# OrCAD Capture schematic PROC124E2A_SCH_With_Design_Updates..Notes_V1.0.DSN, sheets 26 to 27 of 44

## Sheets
26 25. TEST AUTOMATION: size C; title: TEST AUTOMATION
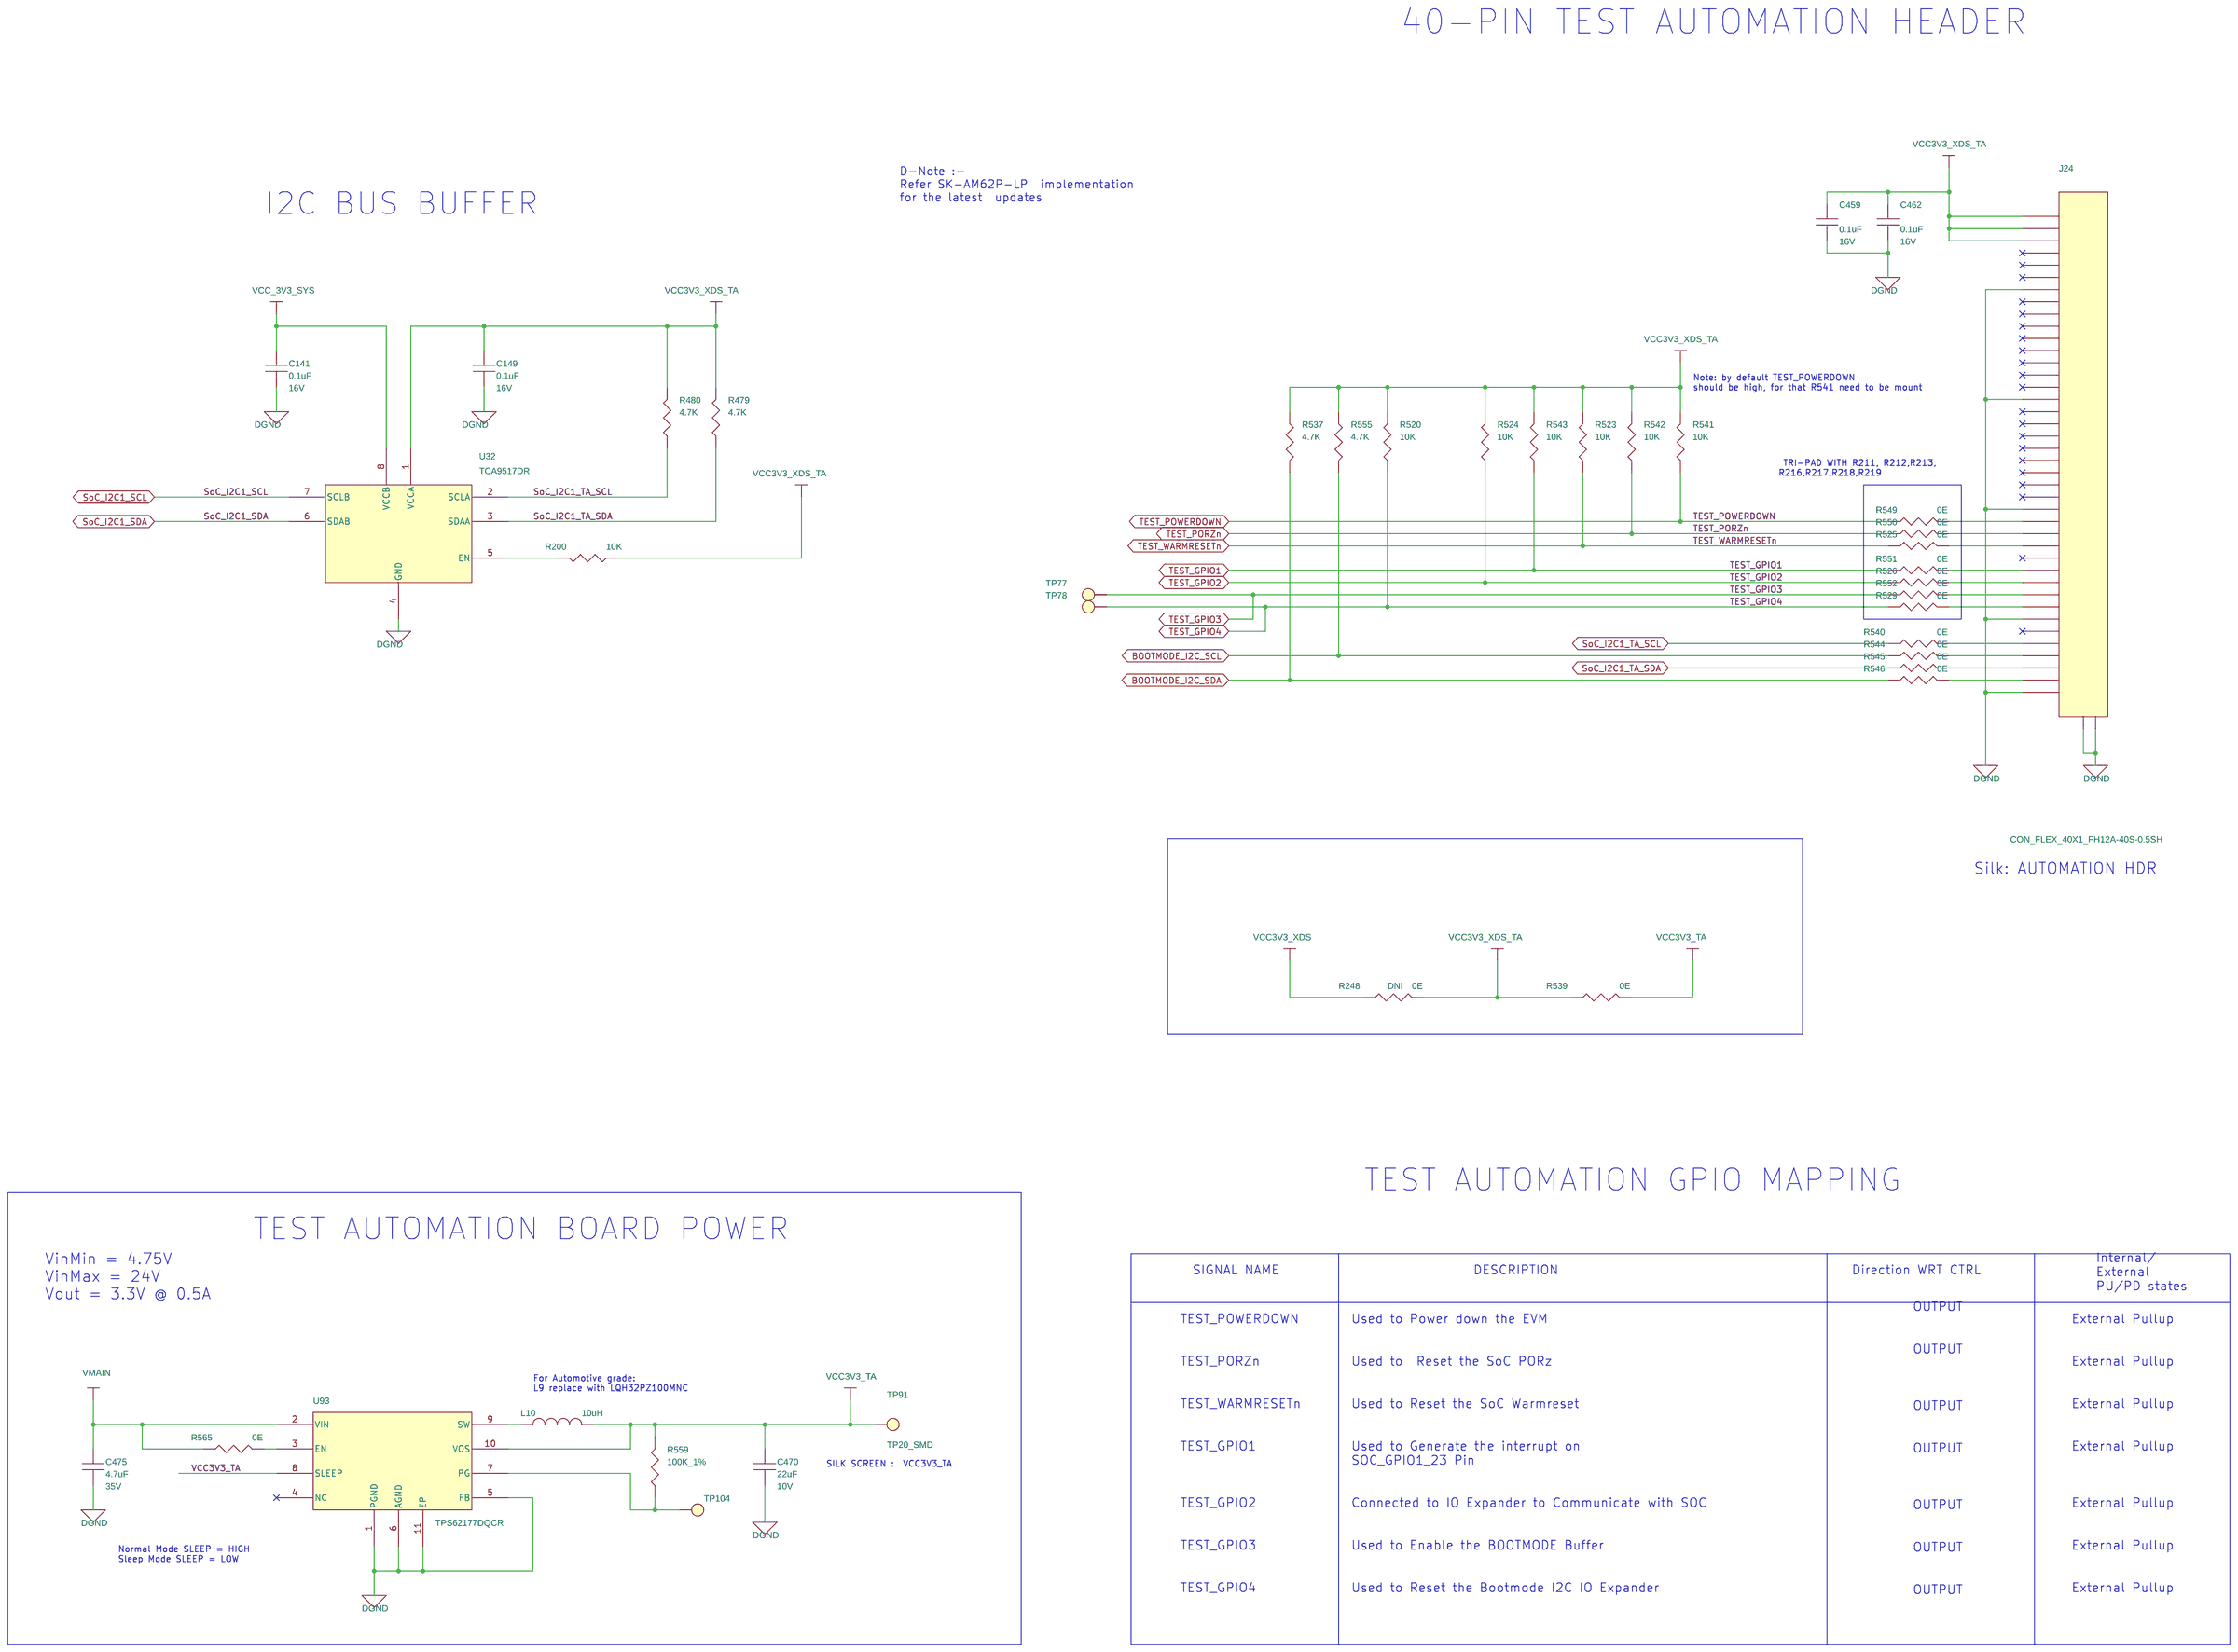
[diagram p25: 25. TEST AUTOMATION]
27 26. BOOT MODE BUFFER & SWITCHES: size C; title: BOOT MODE BUFFER & SWITCHES
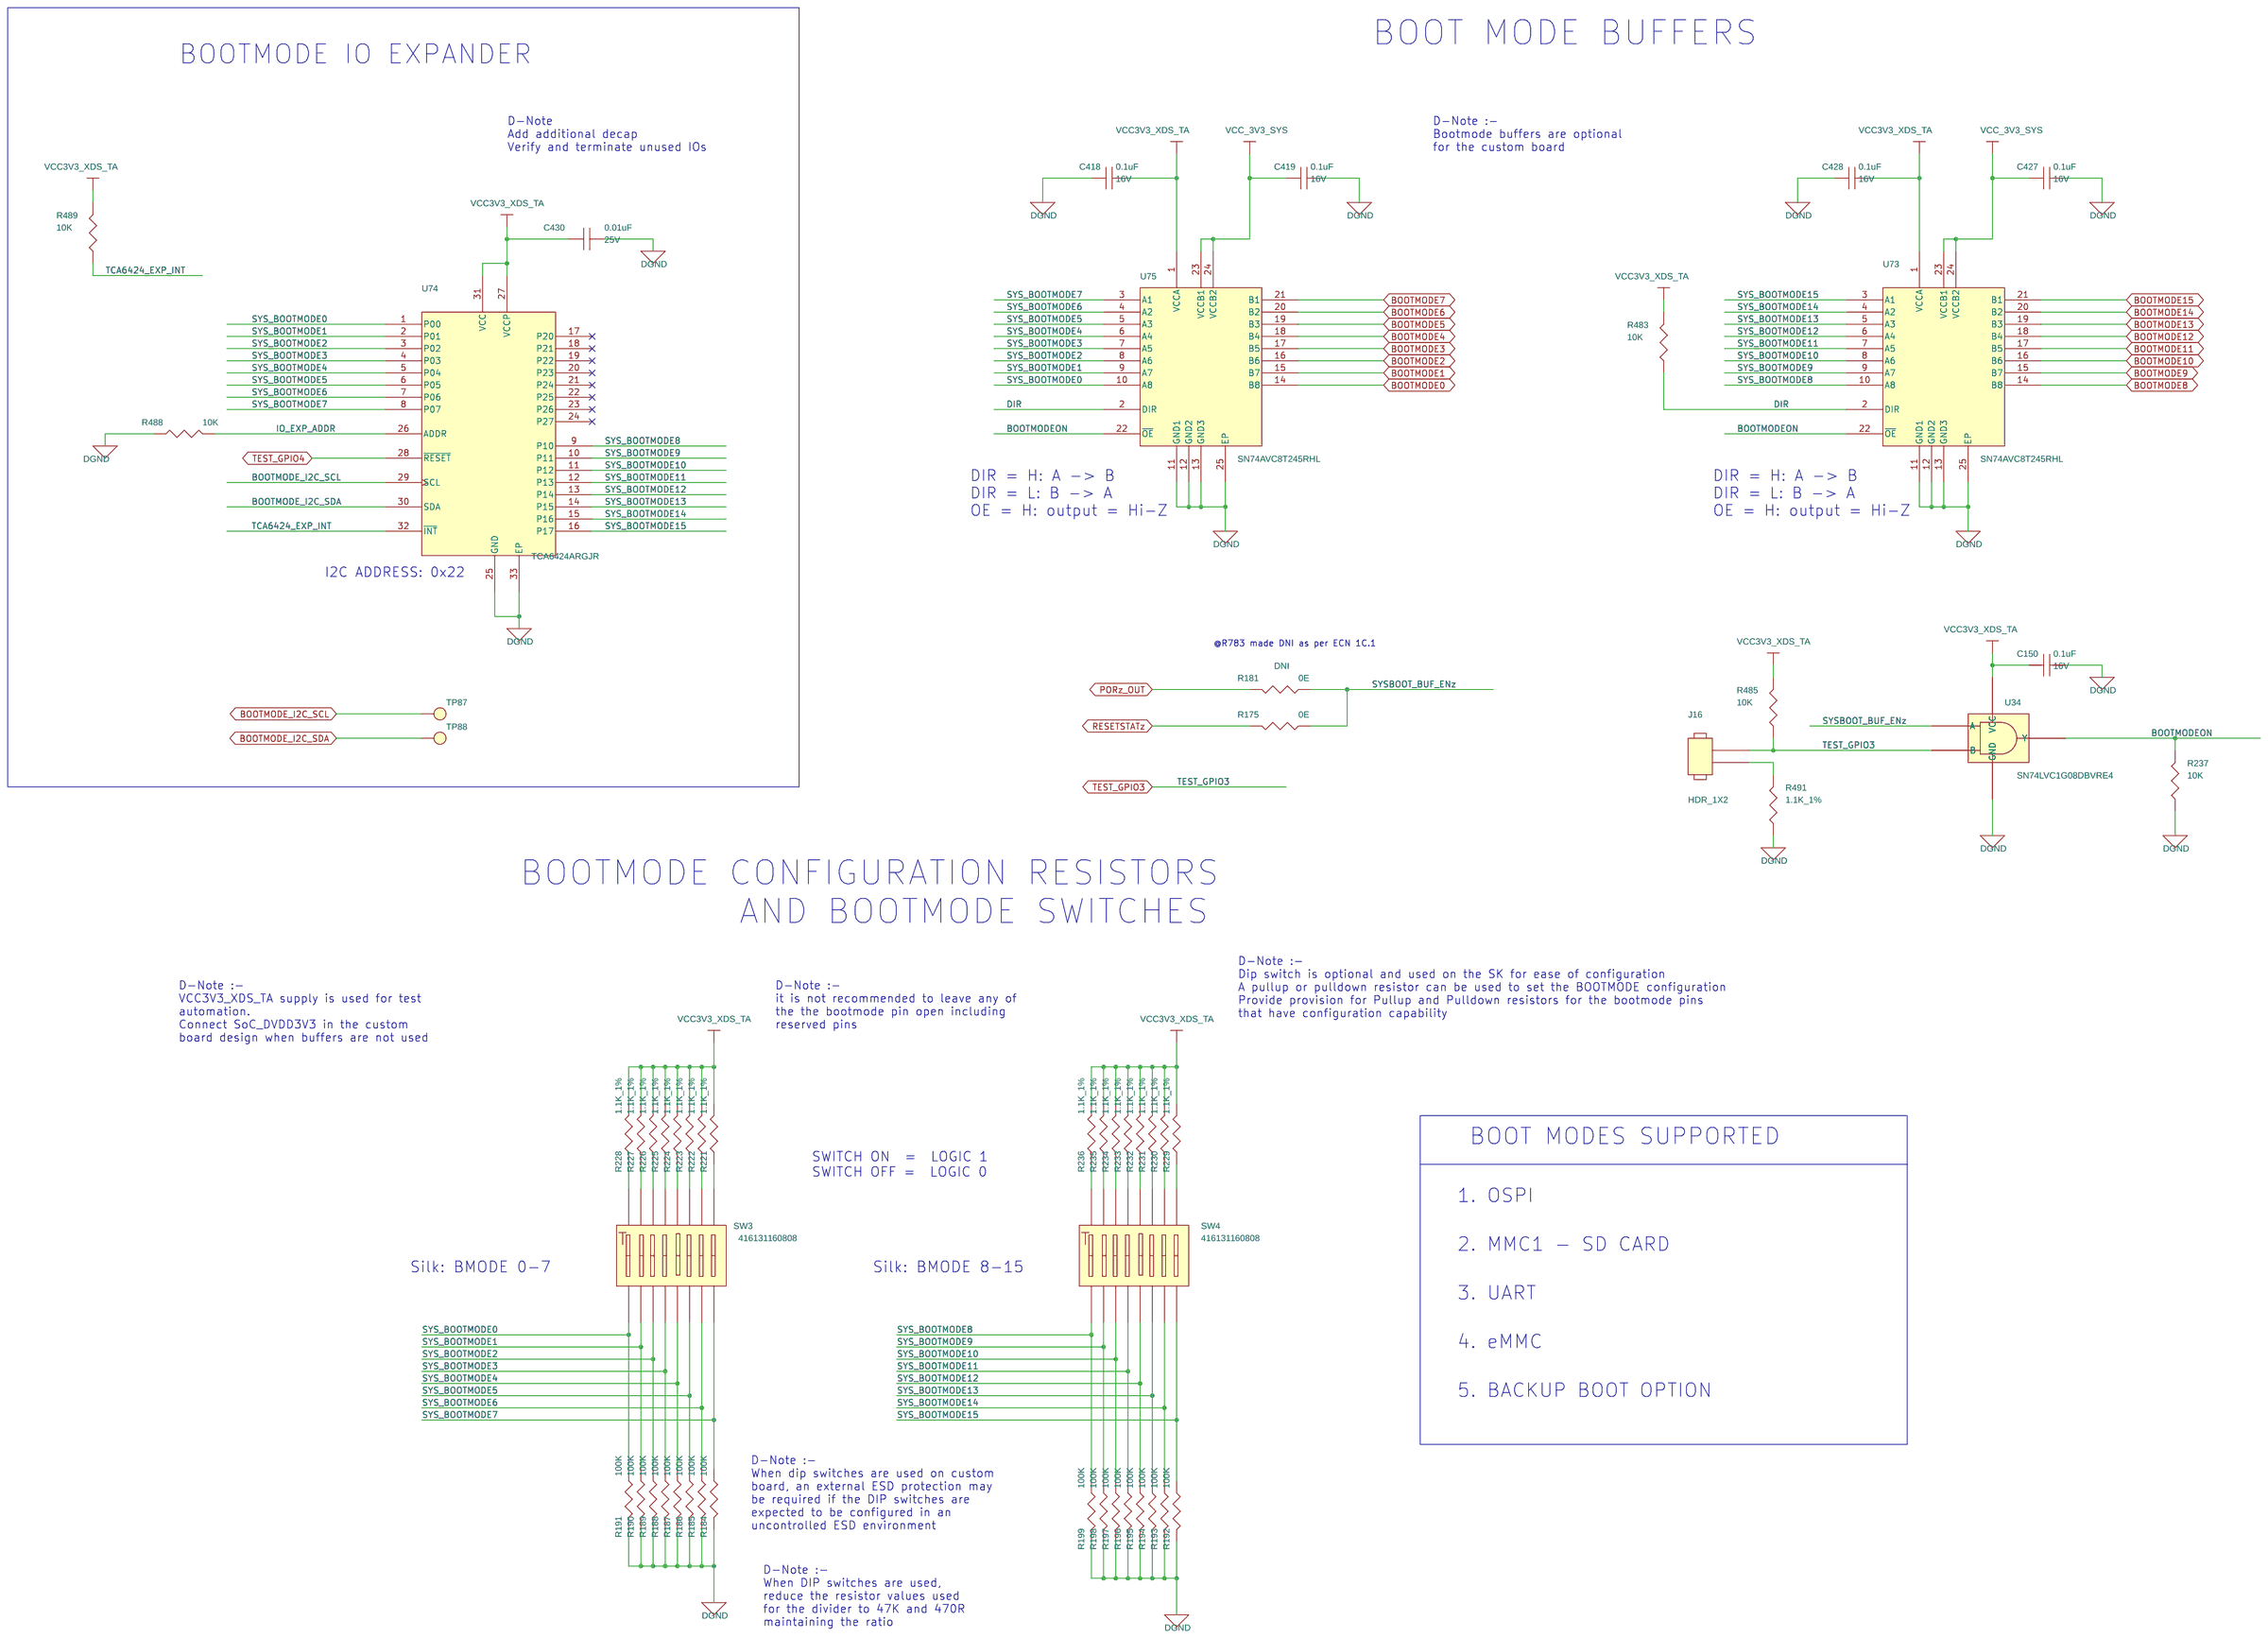
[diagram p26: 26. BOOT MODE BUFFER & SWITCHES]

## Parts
sheet 25. TEST AUTOMATION
C141  0.1uF  [CAP0201_0-5]
C149  0.1uF  [CAP0201_0-5]
C459  0.1uF  [CAP0201_0-5]
C462  0.1uF  [CAP0201_0-5]
C470  22uF  [CAP0603_1]
C475  4.7uF  [CAP0603_1]
J24  CON_FLEX_40X1_FH12A-40S-0.5SH  [CON_FLEX40X1_FH12A_S_R_S]
L10  10uH  [IND_1277AS-H_130X110_SMD_1-2]
R200  10K  [RES0201_0-5]
R248  0E  [RES0805_0-75]
R479  4.7K  [RES0201_0-5]
R480  4.7K  [RES0201_0-5]
R520  10K  [RES0201_0-5]
R523  10K  [RES0201_0-5]
R524  10K  [RES0201_0-5]
R525  0E  [RES0201_0-5]
R526  0E  [RES0201_0-5]
R529  0E  [RES0201_0-5]
R537  4.7K  [RES0201_0-5]
R539  0E  [RES0805_0-75]
R540  0E  [RES0201_0-5]
R541  10K  [RES0201_0-5]
R542  10K  [RES0201_0-5]
R543  10K  [RES0201_0-5]
R544  0E  [RES0201_0-5]
R545  0E  [RES0201_0-5]
R546  0E  [RES0201_0-5]
R549  0E  [RES0201_0-5]
R550  0E  [RES0201_0-5]
R551  0E  [RES0201_0-5]
R552  0E  [RES0201_0-5]
R555  4.7K  [RES0201_0-5]
R559  100K_1%  [RES0402_0-5]
R565  0E  [RES0402_0-5]
TP77  TP20_SMD  [TP20_SMD]
TP78  TP20_SMD  [TP20_SMD]
TP91  TP20_SMD  [TP20_SMD]
TP104  TP20_SMD  [TP20_SMD]
U32  TCA9517DR  [SOIC8_1-8]
U93  TPS62177DQCR  [WSON10_19-68_80X120_0-8]
sheet 26. BOOT MODE BUFFER & SWITCHES
C150  0.1uF  [CAP0201_0-5]
C418  0.1uF  [CAP0201_0-5]
C419  0.1uF  [CAP0201_0-5]
C427  0.1uF  [CAP0201_0-5]
C428  0.1uF  [CAP0201_0-5]
C430  0.01uF  [CAP0201_0-5]
J16  HDR_1X2  [HDR_1X2_90120-0122_S_T_5-6]
R175  0E  [RES0201_0-5]
R181  0E  [RES0201_0-5]
R184  100K  [RES0201_0-5]
R185  100K  [RES0201_0-5]
R186  100K  [RES0201_0-5]
R187  100K  [RES0201_0-5]
R188  100K  [RES0201_0-5]
R189  100K  [RES0201_0-5]
R190  100K  [RES0201_0-5]
R191  100K  [RES0201_0-5]
R192  100K  [RES0201_0-5]
R193  100K  [RES0201_0-5]
R194  100K  [RES0201_0-5]
R195  100K  [RES0201_0-5]
R196  100K  [RES0201_0-5]
R197  100K  [RES0201_0-5]
R198  100K  [RES0201_0-5]
R199  100K  [RES0201_0-5]
R221  1.1K_1%  [RES0201_0-5]
R222  1.1K_1%  [RES0201_0-5]
R223  1.1K_1%  [RES0201_0-5]
R224  1.1K_1%  [RES0201_0-5]
R225  1.1K_1%  [RES0201_0-5]
R226  1.1K_1%  [RES0201_0-5]
R227  1.1K_1%  [RES0201_0-5]
R228  1.1K_1%  [RES0201_0-5]
R229  1.1K_1%  [RES0201_0-5]
R230  1.1K_1%  [RES0201_0-5]
R231  1.1K_1%  [RES0201_0-5]
R232  1.1K_1%  [RES0201_0-5]
R233  1.1K_1%  [RES0201_0-5]
R234  1.1K_1%  [RES0201_0-5]
R235  1.1K_1%  [RES0201_0-5]
R236  1.1K_1%  [RES0201_0-5]
R237  10K  [RES0201_0-5]
R483  10K  [RES0201_0-5]
R485  10K  [RES0201_0-5]
R488  10K  [RES0201_0-5]
R489  10K  [RES0201_0-5]
R491  1.1K_1%  [RES0201_0-5]
SW3  416131160808  [SW16_416131160808_460X230_SMD_2-7]
SW4  416131160808  [SW16_416131160808_460X230_SMD_2-7]
TP87  TP20_SMD  [TP20_SMD]
TP88  TP20_SMD  [TP20_SMD]
U34  SN74LVC1G08DBVRE4  [SOT23-5]
U73  SN74AVC8T245RHL  [QFN24_19-68_220X140_1]
U74  TCA6424ARGJR  [QFN32_19-68_200X200]
U75  SN74AVC8T245RHL  [QFN24_19-68_220X140_1]

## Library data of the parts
C141 C149 C150 C418 C419 C427 C428 C459 C462 = CAP: CAP CERAMIC 0.1uF 16V 10% X5R 0201; Alt_Mfr_name: YAGEO AMERICA; Alt_Mfr_part_number: CC0402KRX5R8BB104; Chkd/date: MANIRAJA/230118; Crtd /date: MANIRAJA/230118; Custom_Duty: 15%; Customs_HS_Code: 85322990; Distributor_name: DIGIKEY; Distributor_part_number: 490-14305-1-ND; Footprint Path: Y:\MIS_DATABASE\Library\ALTIUM_TOOL\PCB_FOOTPRINTS\Altium_Footprint_Lib.PcbLib; Height: 0.33MM; Library Path: Y:\MIS_DATABASE\Library\ALTIUM_TOOL\SCHEMATICS_PARTS\MS_DISCRETE_Library.schlib; Mfr_name: MURATA; Mfr_part_number: GRM033R61C104KE14D; Mistral Part No: 120009030072-R; Package: 0201; Part_type: CAPACITORS\CERAMIC; Project: TI_MAXIE_CPB; RoHS: RoHS; Temperature: -55°C+85°C; Tolerance: 10%; Voltage: 16V; Wattage: NA; Weight: 0.33mg; Datasheet: Y:\MIS_DATABASE\DATASHEETS\CAPACITORS\GRM033R61C104KE14.PDF
C470 = CAP: CAP CERAMIC 22uF 10V 20% X5R 0603; Chkd/date: MANIRAJA/230118; Crtd /date: MANIRAJA/230118; Custom_Duty: 15%; Customs_HS_Code: 85322990; Distributor_name: DIGIKEY; Distributor_part_number: 490-10476-1-ND; Footprint Path: Y:\MIS_DATABASE\Library\ALTIUM_TOOL\PCB_FOOTPRINTS\Altium_Footprint_Lib.PcbLib; Height: 1.00MM; Library Path: Y:\MIS_DATABASE\Library\ALTIUM_TOOL\SCHEMATICS_PARTS\MS_DISCRETE_Library.schlib; Mfr_name: MURATA; Mfr_part_number: GRM188R61A226ME15D; Mistral Part No: 120014100009-R; Package: 0603; Part_type: CAPACITORS\CERAMIC; Project: TI_MAXIE_CPB; RoHS: RoHS; Temperature: -55°C+85°C; Tolerance: 20%; Voltage: 10V; Wattage: NA; Weight: 6.3mg; Datasheet: Y:\MIS_DATABASE\DATASHEETS\CAPACITORS\GRM188R61A226ME15.PDF
C475 = CAP: CAP CERAMIC 4.7uF 35V 20% X5R 0603; Chkd/date: MANIRAJA/120520; Crtd /date: ALVY/120520; Custom_Duty: 15%; Customs_HS_Code: 85322990; Distributor_name: DIGIKEY; Distributor_part_number: 490-11995-1-ND; Footprint Path: Y:\MIS_DATABASE\Library\ALTIUM_TOOL\PCB_FOOTPRINTS\Altium_Footprint_Lib.PcbLib; Height: 1.00MM; Library Path: Y:\MIS_DATABASE\Library\ALTIUM_TOOL\SCHEMATICS_PARTS\MS_DISCRETE_Library.schlib; Mfr_name: MURATA; Mfr_part_number: GRM188R6YA475ME15D; Mistral Part No: 120020050017-R; Package: 0603; Part_type: CAPACITORS\CERAMIC; Project: SD865_NANOSOM; RoHS: RoHS; Temperature: -55°C+85°C; Tolerance: 20%; Voltage: 35V; Wattage: NA; Weight: 6.3mg; Datasheet: Y:\MIS_DATABASE\DATASHEETS\CAPACITORS\GRM188R6YA475ME15.PDF
J24 = CON_FLEX_40X1_FH12A-40S-0.5SH: CON FPC 40X1 0.50MM PITCH RT TOP SMD; Chkd/date: SHREESHAIL/201106; Crtd /date: MAZHAR/171106; Custom_Duty: 24%; Customs_HS_Code: 85369090; Distributor_name: DIGIKEY; Distributor_part_number: HFK40CT-ND; Height: 2.00MM; Mfr_name: HIROSE ELECTRIC EUROPE; Mfr_part_number: FH12A-40S-0.5SH(55); Mistral Part No: 150009030176-R; Package: SMD; Part_type: CONNECTOR\FPC; Project: PMP LCD BOARD; Datasheet: Y:\MIS_DATABASE\DATASHEETS\CONNECTORS\FH12SERIES.PDF
L10 = INDUCTOR: IND POWER 10uH 900mA 20% SMD; Chkd/date: MANIRAJA/200921; Crtd /date: ALVY/200921; Custom_Duty: 24%; Customs_HS_Code: 85369090; Distributor_name: DIGIKEY; Distributor_part_number: 490-10589-1-ND; Footprint Path: Y:\MIS_DATABASE\Library\ALTIUM_TOOL\PCB_FOOTPRINTS\Altium_Footprint_Lib.PcbLib; Height: 1.20MM; Library Path: Y:\MIS_DATABASE\Library\ALTIUM_TOOL\SCHEMATICS_PARTS\MS_DISCRETE_Library.schlib; Mfr_name: MURATA; Mfr_part_number: 1277AS-H-100M=P2; Mistral Part No: 130021090022-R; Package: SMD; Project: TI_AM62x SKEVM_BRD; RoHS: RoHS; Temperature: -40°C+85°C; Tolerance: 20%; Voltage: NA; Wattage: NA; Weight: NA; Datasheet: Y:\MIS_DATABASE\DATASHEETS\DISCRETES\INDUCTORS\MURATA-1277AS-H.PDF
R200 R237 R483 R485 R488 R489 R520 R523 R524 R541-R543 = RESISTOR: RES 10K 1/20W 5% 0201; Chkd/date: MANIRAJA/050517; Crtd /date: MANIRAJA/050517; Custom_Duty: 15%; Customs_HS_Code: 85332119; Distributor_name: DIGIKEY; Distributor_part_number: 311-10KNCT-ND; Footprint Path: Y:\MIS_DATABASE\Library\ALTIUM_TOOL\PCB_FOOTPRINTS\Altium_Footprint_Lib.PcbLib; Height: 0.26MM; Library Path: Y:\MIS_DATABASE\Library\ALTIUM_TOOL\SCHEMATICS_PARTS\MS_DISCRETE_Library.schlib; Mfr_name: YAGEO AMERICA; Mfr_part_number: RC0201JR-0710KL; Mistral Part No: 110010070051-R; Package: 0201; Part_type: RESISTORS\FIXED; Project: GOLDEN-I LITE; RoHS: RoHS; Temperature: -55°C+125°C; Tolerance: 5%; Voltage: NA; Wattage: 1/20W; Weight: 0.17mg; Datasheet: Y:\MIS_DATABASE\DATASHEETS\RESISTORS\RCXXXXL-SER_MAR18.PDF
R248 = RESISTOR: RES 0E 1/8W 5% 0805; Assembly_Instruction: DNI; Chkd/date: VASANTHA/130416; Crtd /date: JEBRAN/020316; Custom_Duty: 15%; Customs_HS_Code: 85332119; Distributor_name: DIGIKEY; Distributor_part_number: 311-0.0ARCT-ND; Footprint Path: Y:\MIS_DATABASE\Library\ALTIUM_TOOL\PCB_FOOTPRINTS\Altium_Footprint_Lib.PcbLib; Height: 0.60MM; Library Path: Y:\MIS_DATABASE\Library\ALTIUM_TOOL\SCHEMATICS_PARTS\MS_DISCRETE_Library.schlib; Mfr_name: YAGEO AMERICA; Mfr_part_number: RC0805JR-070RL; Mistral Part No: 110009030074-R; Package: 0805; Part_type: RESISTORS\FIXED; Project: ZK_BIOMETRIC; RoHS: RoHS; Temperature: -55°C+155°C; Tolerance: 5%; Voltage: NA; Wattage: 1/8W; Weight: 5.5mg; Datasheet: Y:\MIS_DATABASE\DATASHEETS\RESISTORS\RCXXXXL-SER_MAR18.PDF
R479 R480 R537 R555 = RESISTOR: RES 4.7K 1/20W 5% 0201; Chkd/date: MANIRAJA/200921; Crtd /date: ALVY/200921; Custom_Duty: 15%; Customs_HS_Code: 85332119; Distributor_name: DIGIKEY; Distributor_part_number: 311-4.7KNCT-ND; Footprint Path: Y:\MIS_DATABASE\Library\ALTIUM_TOOL\PCB_FOOTPRINTS\Altium_Footprint_Lib.PcbLib; Height: 0.26MM; Library Path: Y:\MIS_DATABASE\Library\ALTIUM_TOOL\SCHEMATICS_PARTS\MS_DISCRETE_Library.schlib; Mfr_name: YAGEO AMERICA; Mfr_part_number: RC0201JR-074K7L; Mistral Part No: 110021090007-R; Package: 0201; Part_type: RESISTORS\FIXED; Project: TI_AM62x SKEVM_BRD; RoHS: RoHS; Temperature: -55°C+125°C; Tolerance: 5%; Voltage: NA; Wattage: 1/20W; Weight: 0.17mg; Datasheet: Y:\MIS_DATABASE\DATASHEETS\RESISTORS\RCXXXXL-SER_MAR18.PDF
R175 R525 R526 R529 R540 R544-R546 R549-R552 = RESISTOR: RES 0E 1/20W 5% 0201; Chkd/date: NAVEED/301214; Crtd /date: MUDDU/120710; Custom_Duty: 15%; Customs_HS_Code: 85332119; Distributor_name: DIGIKEY; Distributor_part_number: 311-0.0NCT-ND; Footprint Path: Y:\MIS_DATABASE\Library\ALTIUM_TOOL\PCB_FOOTPRINTS\Altium_Footprint_Lib.PcbLib; Height: 0.26MM; Library Path: Y:\MIS_DATABASE\Library\ALTIUM_TOOL\SCHEMATICS_PARTS\MS_DISCRETE_Library.schlib; Mfr_name: YAGEO AMERICA; Mfr_part_number: RC0201JR-070RL; Mistral Part No: 110010070067-R; Package: 0201; Part_type: RESISTORS\FIXED; Project: PB_BUGBASE; RoHS: RoHS; Temperature: -55°C+125°C; Tolerance: 5%; Voltage: NA; Wattage: 1/20W; Weight: 0.17mg; Datasheet: Y:\MIS_DATABASE\DATASHEETS\RESISTORS\RCXXXXL-SER_MAR18.PDF
R539 = RESISTOR: RES 0E 1/8W 5% 0805; Chkd/date: VASANTHA/130416; Crtd /date: JEBRAN/020316; Custom_Duty: 15%; Customs_HS_Code: 85332119; Distributor_name: DIGIKEY; Distributor_part_number: 311-0.0ARCT-ND; Footprint Path: Y:\MIS_DATABASE\Library\ALTIUM_TOOL\PCB_FOOTPRINTS\Altium_Footprint_Lib.PcbLib; Height: 0.60MM; Library Path: Y:\MIS_DATABASE\Library\ALTIUM_TOOL\SCHEMATICS_PARTS\MS_DISCRETE_Library.schlib; Mfr_name: YAGEO AMERICA; Mfr_part_number: RC0805JR-070RL; Mistral Part No: 110009030074-R; Package: 0805; Part_type: RESISTORS\FIXED; Project: ZK_BIOMETRIC; RoHS: RoHS; Temperature: -55°C+155°C; Tolerance: 5%; Voltage: NA; Wattage: 1/8W; Weight: 5.5mg; Datasheet: Y:\MIS_DATABASE\DATASHEETS\RESISTORS\RCXXXXL-SER_MAR18.PDF
R559 = RESISTOR: RES 100K 1/10W 1% 0402; Chkd/date: VASANTHA/201216; Crtd /date: MAZHAR/130306; Custom_Duty: 15%; Customs_HS_Code: 85332119; Distributor_name: DIGIKEY; Distributor_part_number: P100KLCT-ND; Footprint Path: Y:\MIS_DATABASE\Library\ALTIUM_TOOL\PCB_FOOTPRINTS\Altium_Footprint_Lib.PcbLib; Height: 0.40MM; Library Path: Y:\MIS_DATABASE\Library\ALTIUM_TOOL\SCHEMATICS_PARTS\MS_DISCRETE_Library.schlib; Mfr_name: PANASONIC-ECG; Mfr_part_number: ERJ-2RKF1003X; Mistral Part No: 110009030187-R; Package: 0402; Part_type: RESISTORS\FIXED; Project: J32; RoHS: RoHS; Temperature: -55°C+155°C; Tolerance: 1%; Voltage: NA; Wattage: 1/10W; Weight: 0.8mg; Datasheet: Y:\MIS_DATABASE\DATASHEETS\RESISTORS\PAN-ERJSER_NOV17.PDF
R565 = RESISTOR: RES 0E 1/16W JUMPER 0402; Chkd/date: VASANTHA/201216; Crtd /date: MUDDU/190810; Custom_Duty: 15%; Customs_HS_Code: 85332119; Distributor_name: DIGIKEY; Distributor_part_number: 541-0.0JCT-ND; Footprint Path: Y:\MIS_DATABASE\Library\ALTIUM_TOOL\PCB_FOOTPRINTS\Altium_Footprint_Lib.PcbLib; Height: 0.40MM; Library Path: Y:\MIS_DATABASE\Library\ALTIUM_TOOL\SCHEMATICS_PARTS\MS_DISCRETE_Library.schlib; Mfr_name: VISHAY; Mfr_part_number: CRCW04020000Z0ED; Mistral Part No: 110010080019-R; Package: 0402; Part_type: RESISTORS\FIXED; Project: PB_BUGBASE; RoHS: RoHS; Temperature: -55°C+155°C; Tolerance: NA; Voltage: NA; Wattage: 1/16W; Weight: 0.65mg; Datasheet: Y:\MIS_DATABASE\DATASHEETS\RESISTORS\CRCW0603.PDF
TP77 TP78 TP87 TP88 TP104 = TESTPOINT: TESTPOINT CIR 20 SMD; Chkd/date: SHREESHAIL/171006; Crtd /date: MAZHAR/171006; Custom_Duty: NA; Customs_HS_Code: NA; Distributor_name: NA; Distributor_part_number: NA; Footprint Path: Y:\MIS_DATABASE\Library\ALTIUM_TOOL\PCB_FOOTPRINTS\Altium_Footprint_Lib.PcbLib; Height: NA; Library Path: Y:\MIS_DATABASE\Library\ALTIUM_TOOL\SCHEMATICS_PARTS\MS_DISCRETE_Library.schlib; MECHANICAL 3D STEP FILE: NA; Mfr_name: LOCAL; Mistral Part No: NA; Package: SMD; Project: BT MODULE_CSRBC04; RoHS: NA; Temperature: NA; Tolerance: NA; Voltage: NA; Wattage: NA; Weight: NA; Datasheet: NA
TP91 = TESTPOINT: TESTPOINT CIR 20 SMD; Chkd/date: SHREESHAIL/171006; Crtd /date: MAZHAR/171006; Custom_Duty: NA; Customs_HS_Code: NA; Distributor_name: NA; Distributor_part_number: NA; Footprint Path: Y:\MIS_DATABASE\Library\ALTIUM_TOOL\PCB_FOOTPRINTS\Altium_Footprint_Lib.PcbLib; Height: NA; Library Path: Y:\MIS_DATABASE\Library\ALTIUM_TOOL\SCHEMATICS_PARTS\MS_DISCRETE_Library.schlib; MECHANICAL 3D STEP FILE: NA; Manufacturer: LOCAL; Mfr_name: LOCAL; Mistral Part No: NA; Package: SMD; Project: BT MODULE_CSRBC04; RoHS: NA; Temperature: NA; Tolerance: NA; Voltage: NA; Wattage: NA; Weight: NA; Datasheet: NA
U32 = TCA9517DGKR_VSSOP8: IC 2-CHANNEL BI-DIR LEVEL-SHIFTING I2C BUS REPEATER SOIC8; Chkd/date: MANIRAJA/171121; Crtd /date: ALVY/161121; Custom_Duty: 15%; Customs_HS_Code: 85423100; Distributor_name: DIGIKEY; Distributor_part_number: 296-39221-1-ND; Footprint Path: Y:\MIS_DATABASE\Library\ALTIUM_TOOL\PCB_FOOTPRINTS\Altium_Footprint_Lib.PcbLib; Height: 1.75MM; Library Path: Y:\MIS_DATABASE\Library\ALTIUM_TOOL\SCHEMATICS_PARTS\MS_MISCINTERFACE_Library.schlib; Mfr_name: TEXAS INSTRUMENTS; Mistral Part No: 141021110017-R; Package: SOIC8; Part_type: ICS\INTERFACE\LEVEL TRANSLATOR; Project: EXCITER MULTI-CH RX UNIT; RoHS: RoHS; Temperature: -40°C+85°C; Tolerance: NA; Voltage: NA; Wattage: NA; Weight: 540mg; Datasheet: Y:\MIS_DATABASE\DATASHEETS\ICS\INTERFACE\TCA9517.PDF
U93 = TPS62177_WSON10: IC 3.3V 0.5A STEP DOWN CONVERTER WITH SLEEP MODE WSON10; Chkd/date: MANIRAJA/170719; Crtd /date: MANIRAJA/170719; Custom_Duty: 15%; Customs_HS_Code: 85423100; Distributor_name: DIGIKEY; Distributor_part_number: 296-41856-1-ND; Footprint Path: Y:\MIS_DATABASE\Library\ALTIUM_TOOL\PCB_FOOTPRINTS\Altium_Footprint_Lib.PcbLib; Height: 0.80MM; Library Path: Y:\MIS_DATABASE\Library\ALTIUM_TOOL\SCHEMATICS_PARTS\MS_MISCPOWER_Library.schlib; Mfr_name: TEXAS INSTRUMENTS; Mistral Part No: 142019070007-R; Package: WSON10; Part_type: ICS\POWER\DC-DC CONVERTER; Project: TI_MAXIE_CPB; RoHS: RoHS; Temperature: -40°C+85°C; Tolerance: NA; Voltage: NA; Wattage: NA; Weight: 15mg; Datasheet: Y:\MIS_DATABASE\DATASHEETS\ICS\POWER\TPS62177.PDF
C430 = CAP: CAP CERAMIC 0.01uF 25V 10% X5R 0201; Chkd/date: MANIRAJA/230118; Crtd /date: MANIRAJA/230118; Custom_Duty: 15%; Customs_HS_Code: 85322990; Distributor_name: DIGIKEY; Distributor_part_number: GRM033R61E103KA12J-ND; Footprint Path: Y:\MIS_DATABASE\Library\ALTIUM_TOOL\PCB_FOOTPRINTS\Altium_Footprint_Lib.PcbLib; Height: 0.33MM; Library Path: Y:\MIS_DATABASE\Library\ALTIUM_TOOL\SCHEMATICS_PARTS\MS_DISCRETE_Library.schlib; Mfr_name: MURATA; Mfr_part_number: GRM033R61E103KA12J; Mistral Part No: 120018010007-R; Package: 0201; Part_type: CAPACITORS\CERAMIC; Project: TI_MAXIE_CPB; RoHS: RoHS; Temperature: -55°C+85°C; Tolerance: 10%; Voltage: 25V; Wattage: NA; Weight: 0.33mg; Datasheet: Y:\MIS_DATABASE\DATASHEETS\CAPACITORS\GRM033R61E103KA12.PDF
J16 = HEADER_2X1: CON HDR 1X2 2.54MM PITCH ST TH; Chkd/date: NAVEED/210714; Crtd /date: USMAN/031012; Custom_Duty: 24%; Customs_HS_Code: 85369090; Distributor_name: DIGIKEY; Distributor_part_number: WM8072-ND; Footprint Path: Y:\MIS_DATABASE\Library\ALTIUM_TOOL\PCB_FOOTPRINTS\Altium_Footprint_Lib.PcbLib; Height: 5.60MM; Library Path: Y:\MIS_DATABASE\Library\ALTIUM_TOOL\SCHEMATICS_PARTS\MS_CONNECTOR_Library.schlib; Mfr_name: MOLEX; Mfr_part_number: 90120-0122; Mistral Part No: 150012100005-R; Package: THRU-HOLE; Part_type: CONNECTOR\HEADERS; Project: NPOL_FEP; RoHS: RoHS; Temperature: -55°C+125°C; Tolerance: NA; Voltage: NA; Wattage: NA; Weight: 122mg; Datasheet: Y:\MIS_DATABASE\DATASHEETS\CONNECTORS\90120-XX.PDF
R181 = RESISTOR: RES 0E 1/20W 5% 0201; Assembly_Instruction: DNI; Chkd/date: NAVEED/301214; Crtd /date: MUDDU/120710; Custom_Duty: 15%; Customs_HS_Code: 85332119; Distributor_name: DIGIKEY; Distributor_part_number: 311-0.0NCT-ND; Footprint Path: Y:\MIS_DATABASE\Library\ALTIUM_TOOL\PCB_FOOTPRINTS\Altium_Footprint_Lib.PcbLib; Height: 0.26MM; Library Path: Y:\MIS_DATABASE\Library\ALTIUM_TOOL\SCHEMATICS_PARTS\MS_DISCRETE_Library.schlib; Mfr_name: YAGEO AMERICA; Mfr_part_number: RC0201JR-070RL; Mistral Part No: 110010070067-R; Package: 0201; Part_type: RESISTORS\FIXED; Project: PB_BUGBASE; RoHS: RoHS; Temperature: -55°C+125°C; Tolerance: 5%; Voltage: NA; Wattage: 1/20W; Weight: 0.17mg; Datasheet: Y:\MIS_DATABASE\DATASHEETS\RESISTORS\RCXXXXL-SER_MAR18.PDF
R184-R199 = RESISTOR: RES 100K 1/20W 5% 0201; Chkd/date: PRAVEEN/080922; Crtd /date: TAMILARASU/080922; Custom_Duty: 15%; Customs_HS_Code: 85332119; Distributor_name: DIGIKEY; Distributor_part_number: P123223CT-ND; Footprint Path: Y:\MIS_DATABASE\Library\ALTIUM_TOOL\PCB_FOOTPRINTS\Altium_Footprint_Lib.PcbLib; Height: 0.26MM; Library Path: Y:\MIS_DATABASE\Library\ALTIUM_TOOL\SCHEMATICS_PARTS\MS_DISCRETE_Library.schlib; Mfr_name: PANASONIC-ECG; Mfr_part_number: ERJ-1GNJ104C; Mistral Part No: 110022090005-R; Package: 0201; Part_type: RESISTORS\FIXED; Project: SK AM62Q LP EVM BRD; RoHS: RoHS; Temperature: -55°C+125°C; Tolerance: 5%; Voltage: NA; Wattage: 1/20W; Weight: 0.15mg; Datasheet: Y:\MIS_DATABASE\DATASHEETS\RESISTORS\PAN-ERJSER_NOV17.PDF
R221-R236 R491 = RESISTOR: RES 1.1K 1/20W 1% 0201; Chkd/date: PRAVEEN/080922; Crtd /date: TAMILARASU/080922; Custom_Duty: 15%; Customs_HS_Code: 85332119; Distributor_name: DIGIKEY; Distributor_part_number: P122674CT-ND; Footprint Path: Y:\MIS_DATABASE\Library\ALTIUM_TOOL\PCB_FOOTPRINTS\Altium_Footprint_Lib.PcbLib; Height: 0.26MM; Library Path: Y:\MIS_DATABASE\Library\ALTIUM_TOOL\SCHEMATICS_PARTS\MS_DISCRETE_Library.schlib; Mfr_name: PANASONIC-ECG; Mfr_part_number: ERJ-1GNF1101C; Mistral Part No: 110022090004-R; Package: 0201; Part_type: RESISTORS\FIXED; Project: SK AM62Q LP EVM BRD; RoHS: RoHS; Temperature: -55°C+125°C; Tolerance: 1%; Voltage: NA; Wattage: 1/20W; Weight: 0.15mg; Datasheet: Y:\MIS_DATABASE\DATASHEETS\RESISTORS\PAN-ERJSER_NOV17.PDF
SW3 SW4 = SW16_CHS-08A: SWITCH SLIDE SPST ST SMD; Chkd/date: MANIRAJA/051020; Crtd /date: ALVY/011020; Custom_Duty: 24%; Customs_HS_Code: 85369090; Distributor_name: DIGIKEY; Distributor_part_number: 732-3857-1-ND; Footprint Path: Y:\MIS_DATABASE\Library\ALTIUM_TOOL\PCB_FOOTPRINTS\Altium_Footprint_Lib.PcbLib; Height: 2.65MM; Library Path: Y:\MIS_DATABASE\Library\ALTIUM_TOOL\SCHEMATICS_PARTS\MS_SWITCH_Library.schlib; Mfr_name: WURTH ELECTRONICS; Mistral Part No: 130020100001-R; Package: SMD; Part_type: ELECTRO-MECHANICAL\SWITCH; Project: AM64X_SKEVM; RoHS: RoHS; Temperature: -40°C+85°C; Tolerance: NA; Voltage: NA; Wattage: NA; Weight: 281.7mg; Datasheet: Y:\MIS_DATABASE\DATASHEETS\MISC\SWITCHES\4161311608XX.PDF
U34 = SN74LVC1G08DBVRE4_SOT23-5: IC SINGLE 2-INPUT POSITIVE AND GATE SOT23-5; Chkd/date: SUHAS/221010; Crtd /date: USMAN/151008; Custom_Duty: 15%; Customs_HS_Code: 85423100; Distributor_name: DIGIKEY; Distributor_part_number: SN74LVC1G08DBVRE4-ND; Height: 1.45MM; Mfr_name: TEXAS INSTRUMENTS; Mistral Part No: 141009060026-R; Part_type: ICS\DIGITAL\GATES; Project: KHAN_MAIN; RoHS: Sb/ Br FREE; Temperature: -40°C+85°C; Datasheet: Y:\MIS_DATABASE\DATASHEETS\ICS\DIGITAL\GATES\SN74LVC1G08.PDF
U73 U75 = SN74AVC8T245RHL_QFN24: IC BUS TRANSCEIVER 8-BIT DUAL-SUPPLY QFN24; Chkd/date: VASANTHA/231216; Crtd /date: BAVISH/290411; Custom_Duty: 15%; Customs_HS_Code: 85423100; Distributor_name: DIGIKEY; Distributor_part_number: 296-17859-1-ND; Height: 1.00MM; Mfr_name: TEXAS INSTRUMENTS; Mfr_part_number: SN74AVC8T245RHLR; Mistral Part No: 143011040001-R; Package: QFN24; Part_type: ICS\TELECOM\TRANSCEIVER; Project: OMAPL1_PEC20; RoHS: RoHS; Temperature: -40°C+85°C; Tolerance: NA; Voltage: NA; Wattage: NA; Weight: NA; Datasheet: Y:\MIS_DATABASE\DATASHEETS\ICS\DIGITAL\BUSTRANSCEIVER\SN74AVC8T245.PDF
U74 = TCA6424ARGJR_QFN32: IC I2C I/O EXPANDER 24B UQFN32; Chkd/date: NAVEED/100715; Crtd /date: NAVEED/100914; Custom_Duty: 15%; Customs_HS_Code: 85423100; Distributor_name: DIGIKEY; Distributor_part_number: 296-27844-1-ND; Height: 0.60MM; Mfr_name: TEXAS INSTRUMENTS; Mistral Part No: 141014090009-R; Package: UQFN32; Part_type: ICS\DIGITAL\BUSTRANSCEIVER; Project: ZK_BIOMETRIC; RoHS: RoHS; Temperature: -40°C+85°C; Weight: NA; Datasheet: Y:\MIS_DATABASE\DATASHEETS\ICS\DIGITAL\BUSTRANSCEIVER\TCA6424AR.PDF

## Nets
DGND: C141.2 C149.2 C150.2 C418.1 C419.2 C427.2 C428.1 C430.1 C459.2 C462.2 C470.2 C475.2 J24.7 J24.16 J24.25 J24.34 J24.40 J24.41 J24.42 R184.2 R185.2 R186.2 R187.2 R188.2 R189.2 R190.2 R191.2 R192.2 R193.2 R194.2 R195.2 R196.2 R197.2 R198.2 R199.2 R237.1 R488.2 R491.1 U32.4(GND) U34.3(GND) U73.11(GND1) U73.12(GND2) U73.13(GND3) U73.25(EP) U74.25(GND) U74.33(EP) U75.11(GND1) U75.12(GND2) U75.13(GND3) U75.25(EP) U93.1(PGND) U93.5(FB) U93.6(AGND) U93.11(EP) ; also on sheet 1 2 3 4 13 14 15 16 17 18 19 20 21 22 23 24 25 28 29 30 31 32 33 34 35 36 37 38 39 40 41 42 43
VCC3V3_TA: C470.1 L10.2 R539.2 R559.2 TP91.1(TP) U93.8(SLEEP) U93.10(VOS)
VCC3V3_XDS: R248.1 ; also on sheet 28 29
VCC3V3_XDS_TA: C149.1 C150.1 C418.2 C428.2 C430.2 C459.1 C462.1 J24.1 J24.2 J24.3 R200.2 R221.2 R222.2 R223.2 R224.2 R225.2 R226.2 R227.2 R228.2 R229.2 R230.2 R231.2 R232.2 R233.2 R234.2 R235.2 R236.2 R248.2 R479.1 R480.1 R483.2 R485.2 R489.2 R520.2 R523.2 R524.2 R537.1 R539.1 R541.2 R542.2 R543.2 R555.1 U32.1(VCCA) U34.5(VCC) U73.1(VCCA) U74.27(VCCP) U74.31(VCC) U75.1(VCCA)
VCC_3V3_SYS: C141.1 C419.1 C427.1 U32.8(VCCB) U73.23(VCCB1) U73.24(VCCB2) U75.23(VCCB1) U75.24(VCCB2) ; also on sheet 1 4 15 16 19 20 21 23 24 29 30 31 32 33 34 36 37 38 39 40 41 42 43
BOOTMODE0: U75.14(B8) ; also on sheet 32
BOOTMODE1: U75.15(B7) ; also on sheet 32
BOOTMODE2: U75.16(B6) ; also on sheet 32
BOOTMODE3: U75.17(B5) ; also on sheet 32
BOOTMODE4: U75.18(B4) ; also on sheet 32
BOOTMODE5: U75.19(B3) ; also on sheet 32
BOOTMODE6: U75.20(B2) ; also on sheet 32
BOOTMODE7: U75.21(B1) ; also on sheet 32
BOOTMODE8: U73.14(B8) ; also on sheet 32
BOOTMODE9: U73.15(B7) ; also on sheet 32
BOOTMODE10: U73.16(B6) ; also on sheet 32
BOOTMODE11: U73.17(B5) ; also on sheet 32
BOOTMODE12: U73.18(B4) ; also on sheet 32
BOOTMODE13: U73.19(B3) ; also on sheet 32
BOOTMODE14: U73.20(B2) ; also on sheet 32
BOOTMODE15: U73.21(B1) ; also on sheet 32
BOOTMODE_I2C_SCL: R544.1 R555.2 TP87.1(TP) U74.29(SCL) ; also on sheet 28
BOOTMODE_I2C_SDA: R537.2 R546.1 TP88.1(TP) U74.30(SDA) ; also on sheet 28
BOOTMODEON: R237.2 U34.4(Y) U73.22(~{OE}) U75.22(~{OE})
DIR: R483.1 U73.2(DIR) U75.2(DIR)
IO_EXP_ADDR: R488.1 U74.26(ADDR)
PORz_OUT: R181.2 ; also on sheet 1 21 24 42
RESETSTATz: R175.2 ; also on sheet 1 4 20 21 22 24 32 37 38 39 40 41 42
SOC_I2C1_SCL: U32.7(SCLB) ; also on sheet 16 23 39 40 41 42
SOC_I2C1_SDA: U32.6(SDAB) ; also on sheet 16 23 39 40 41 42
SoC_I2C1_TA_SCL: R480.2 R540.1 U32.2(SCLA) ; also on sheet 28
SoC_I2C1_TA_SDA: R479.2 R545.1 U32.3(SDAA) ; also on sheet 28
SYS_BOOTMODE0: R191.1 SW3.1 U74.1(P00) U75.10(A8)
SYS_BOOTMODE1: R190.1 SW3.2 U74.2(P01) U75.9(A7)
SYS_BOOTMODE2: R189.1 SW3.3 U74.3(P02) U75.8(A6)
SYS_BOOTMODE3: R188.1 SW3.4 U74.4(P03) U75.7(A5)
SYS_BOOTMODE4: R187.1 SW3.5 U74.5(P04) U75.6(A4)
SYS_BOOTMODE5: R186.1 SW3.6 U74.6(P05) U75.5(A3)
SYS_BOOTMODE6: R185.1 SW3.7 U74.7(P06) U75.4(A2)
SYS_BOOTMODE7: R184.1 SW3.8 U74.8(P07) U75.3(A1)
SYS_BOOTMODE8: R199.1 SW4.1 U73.10(A8) U74.9(P10)
SYS_BOOTMODE9: R198.1 SW4.2 U73.9(A7) U74.10(P11)
SYS_BOOTMODE10: R197.1 SW4.3 U73.8(A6) U74.11(P12)
SYS_BOOTMODE11: R196.1 SW4.4 U73.7(A5) U74.12(P13)
SYS_BOOTMODE12: R195.1 SW4.5 U73.6(A4) U74.13(P14)
SYS_BOOTMODE13: R194.1 SW4.6 U73.5(A3) U74.14(P15)
SYS_BOOTMODE14: R193.1 SW4.7 U73.4(A2) U74.15(P16)
SYS_BOOTMODE15: R192.1 SW4.8 U73.3(A1) U74.16(P17)
SYSBOOT_BUF_ENz: R175.1 R181.1 U34.1(A)
TCA6424_EXP_INT: R489.1 U74.32(~{INT})
TEST_GPIO1: R543.1 R551.1 ; also on sheet 28 43
TEST_GPIO2: R524.1 R526.1 ; also on sheet 28 39
TEST_GPIO3: J16.1 R485.1 R552.1 TP77.1(TP) U34.2(B) ; also on sheet 28
TEST_GPIO4: R520.1 R529.1 TP78.1(TP) U74.28(~{RESET}) ; also on sheet 28
TEST_PORZn: R542.1 R550.1 ; also on sheet 28 42
TEST_POWERDOWN: R541.1 R549.1 ; also on sheet 4 14 28
TEST_WARMRESETn: R523.1 R525.1 ; also on sheet 28 43
VMAIN: C475.1 R565.1 U93.2(VIN) ; also on sheet 13 14 15
N16990175: J24.27 R550.2
N16990176: J24.30 R551.2
N16990179: J24.31 R526.2
N16990180: J24.32 R552.2
N16990215: R200.1 U32.5(EN)
N16990246: J24.26 R549.2
N16990247: J24.28 R525.2
N16990252: J24.33 R529.2
N17078351: R225.1 SW3.13
N17078353: R226.1 SW3.14
N17078355: R227.1 SW3.15
N17078357: R228.1 SW3.16
N17078758: R231.1 SW4.11
N17078760: R232.1 SW4.12
N17078762: R233.1 SW4.13
N17078764: R234.1 SW4.14
N17078766: R229.1 SW4.9
N17078768: R230.1 SW4.10
N17078770: R235.1 SW4.15
N17078778: R236.1 SW4.16
N17078974: J16.2 R491.2
N17084256: R221.1 SW3.9
N17084257: R222.1 SW3.10
N17084258: R223.1 SW3.11
N17084259: R224.1 SW3.12
N17253649: L10.1 U93.9(SW)
N17253673: R559.1 TP104.1(TP) U93.7(PG)
N17253694: R565.2 U93.3(EN)
N18374804: J24.36 R540.2
N18374807: J24.37 R544.2
N18374810: J24.38 R545.2
N18374813: J24.39 R546.2

Not connected (* = marked no-connect by the designer): J24 4* 5* 6* 8* 9* 10* 11* 12* 13* 14* 15* 17* 18* 19* 20* 21* 22* 23* 24* 29* 35*; U74 17(P20)* 18(P21)* 19(P22)* 20(P23)* 21(P24)* 22(P25)* 23(P26)* 24(P27)*; U93 4(NC)*

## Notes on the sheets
sheet 26
- 40-PIN TEST AUTOMATION HEADER
- D-Note :-
  Refer SK-AM62P-LP  implementation
  for the latest  updates
- I2C BUS BUFFER
- Note: by default TEST_POWERDOWN
  should be high, for that R541 need to be mount
- TRI-PAD WITH R211, R212,R213,
  R216,R217,R218,R219
- Silk: AUTOMATION HDR
- TEST AUTOMATION GPIO MAPPING
- TEST AUTOMATION BOARD POWER
- VinMin = 4.75V
  VinMax = 24V
  Vout = 3.3V @ 0.5A
- Internal/
  External
  PU/PD states
- SIGNAL NAME
- DESCRIPTION
- Direction WRT CTRL
- OUTPUT
  OUTPUT
  OUTPUT
  OUTPUT
  OUTPUT
  OUTPUT
  OUTPUT
- TEST_POWERDOWN
  TEST_PORZn
  TEST_WARMRESETn
  TEST_GPIO1
  TEST_GPIO2
  TEST_GPIO3
  TEST_GPIO4
- Used to Power down the EVM
  Used to  Reset the SoC PORz
  Used to Reset the SoC Warmreset
  Used to Generate the interrupt on
  SOC_GPIO1_23 Pin
  Connected to IO Expander to Communicate with SOC
  Used to Enable the BOOTMODE Buffer
  Used to Reset the Bootmode I2C IO Expander
- External Pullup
  External Pullup
  External Pullup
  External Pullup
  External Pullup
  External Pullup
  External Pullup
- For Automotive grade:
  L9 replace with LQH32PZ100MNC
- SILK SCREEN :  VCC3V3_TA
- Normal Mode SLEEP = HIGH
  Sleep Mode SLEEP = LOW
sheet 27
- BOOT MODE BUFFERS
- BOOTMODE IO EXPANDER
- D-Note
  Add additional decap
  Verify and terminate unused IOs
- D-Note :-
  Bootmode buffers are optional
  for the custom board
- DIR = H: A -> B
  DIR = L: B -> A
  OE = H: output = Hi-Z
- DIR = H: A -> B
  DIR = L: B -> A
  OE = H: output = Hi-Z
- I2C ADDRESS: 0x22
- @R783 made DNI as per ECN 1C.1
- BOOTMODE CONFIGURATION RESISTORS
              AND BOOTMODE SWITCHES
- D-Note :-
  Dip switch is optional and used on the SK for ease of configuration
  A pullup or pulldown resistor can be used to set the BOOTMODE configuration
  Provide provision for Pullup and Pulldown resistors for the bootmode pins
  that have configuration capability
- D-Note :-
  VCC3V3_XDS_TA supply is used for test
  automation.
  Connect SoC_DVDD3V3 in the custom
  board design when buffers are not used
- D-Note :-
  it is not recommended to leave any of
  the the bootmode pin open including
  reserved pins
- BOOT MODES SUPPORTED
- SWITCH ON  =  LOGIC 1
  SWITCH OFF =  LOGIC 0
- 1. OSPI
- 2. MMC1 - SD CARD
- Silk: BMODE 0-7
- Silk: BMODE 8-15
- 3. UART
- 4. eMMC
- 5. BACKUP BOOT OPTION
- D-Note :-
  When dip switches are used on custom
  board, an external ESD protection may
  be required if the DIP switches are
  expected to be configured in an
  uncontrolled ESD environment
- D-Note :-
  When DIP switches are used,
  reduce the resistor values used
  for the divider to 47K and 470R
  maintaining the ratio
